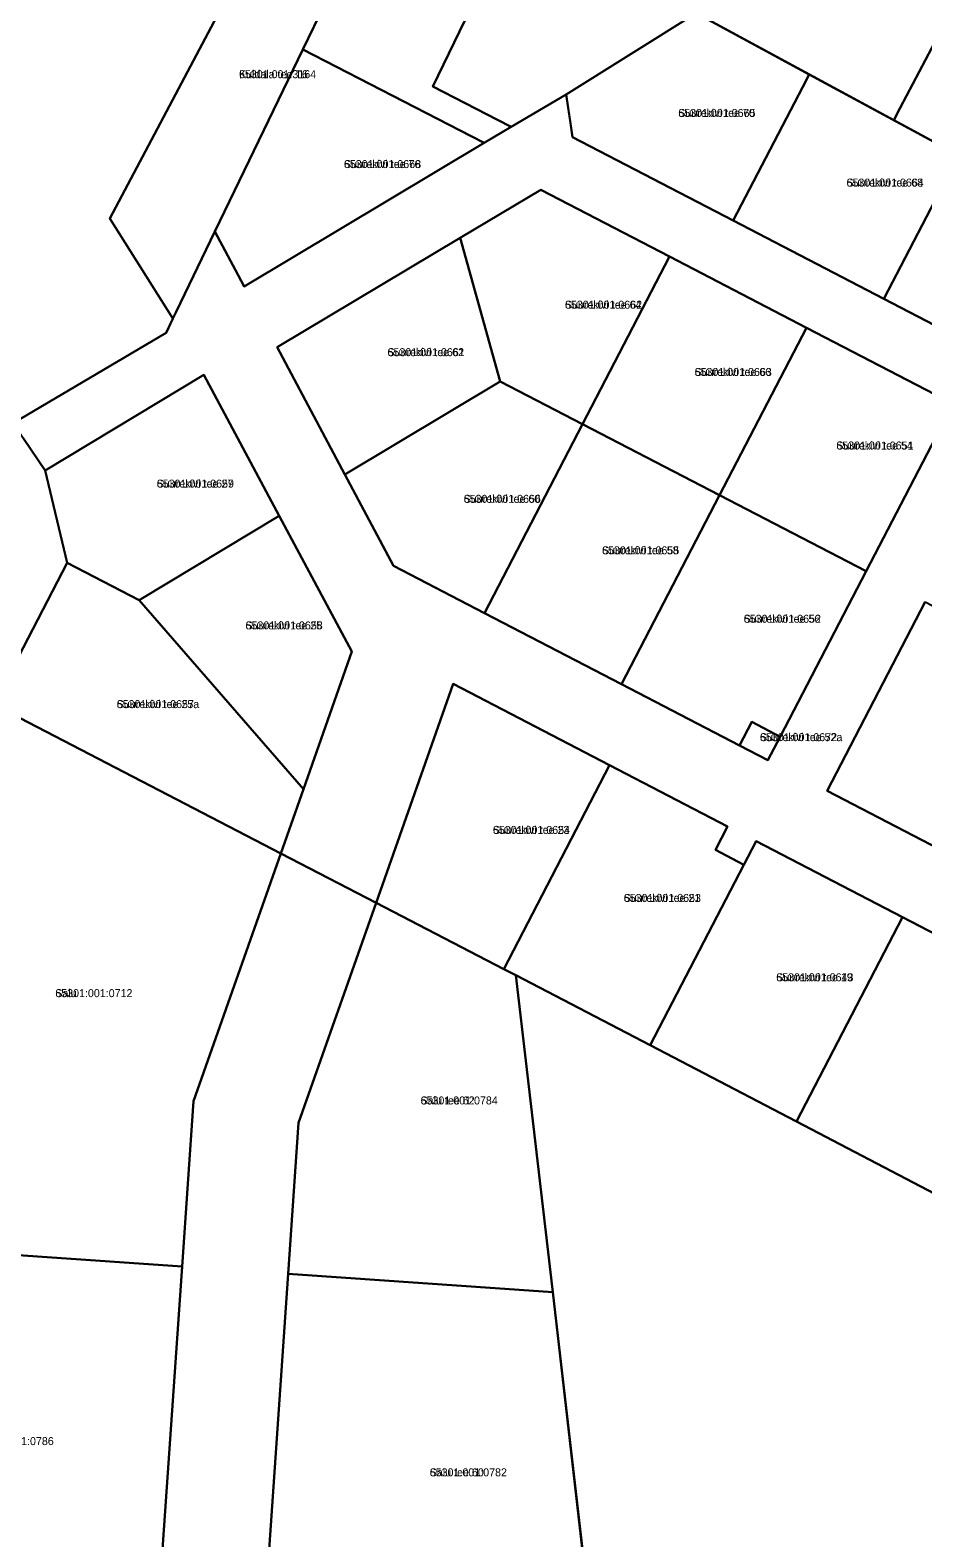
# Model space of a CAD drawing. Extents: x 543236 to 563717, y 6566033 to 6588992.
# Drawn here: x 545424.5 to 545592.2, y 6584755.7 to 6585039 of the extents above; entities that cross this region are included whole.
import ezdxf

# ---------------------------------------------------------------- set-up
doc = ezdxf.new("R2010")
doc.units = 0
for name, color, linetype in [('L_AADRESS', 7, 'Continuous'), ('PIIR', 7, 'Continuous'), ('TUNNUS', 7, 'Continuous')]:
    doc.layers.add(name, color=color, linetype=linetype)

msp = doc.modelspace()

# ---------------------------------------------------------------- linework, layer by layer
at = {"layer": 'PIIR'}
for points in [[(545473.62, 6585068.23), (545439.46, 6585003.59), (545451.28, 6584984.82), (545449.99, 6584982.15), (545421.27, 6584965.16), (545372.09, 6584935.15), (545368.98, 6584936.89), (545361.63, 6584940.84), (545358.12, 6584942.6), (545293.55, 6584977.38), (545384.58, 6585115.49)], [(545493.54, 6585072.24), (545515.81, 6585060.87), (545515.15, 6585059.5), (545500.12, 6585028.41), (545512.27, 6585022.16), (545514.85, 6585020.84), (545509.79, 6585017.81), (545507.34, 6585019.08), (545475.7, 6585035.34), (545492.9, 6585070.91)], [(545473.62, 6585068.23), (545487.93, 6585060.63), (545475.7, 6585035.34), (545459.19, 6585001.19), (545451.9, 6584986.11), (545451.28, 6584984.82), (545439.46, 6585003.59)], [(545515.81, 6585060.87), (545550.91, 6585042.94), (545549.62, 6585042.17), (545525.19, 6585026.92), (545514.85, 6585020.84), (545512.27, 6585022.16), (545500.12, 6585028.41), (545515.15, 6585059.5)], [(545549.62, 6585042.17), (545570.85, 6585030.7), (545569.63, 6585028.37), (545556.58, 6585003.22), (545526.38, 6585018.89), (545525.92, 6585022.04), (545525.19, 6585026.92)], [(545598.65, 6585044.77), (545610.33, 6585038.63), (545599.54, 6585018.11), (545598.92, 6585015.53), (545586.73, 6585022.12), (545587.93, 6585024.39)], [(545475.7, 6585035.34), (545507.34, 6585019.08), (545509.79, 6585017.81), (545464.67, 6584990.84), (545463.54, 6584992.98), (545459.19, 6585001.19)], [(545570.85, 6585030.7), (545598.92, 6585015.53), (545597.72, 6585013.22), (545584.89, 6584988.52), (545556.58, 6585003.22), (545569.63, 6585028.37)], [(545598.92, 6585015.53), (545625.66, 6585001.08), (545624.52, 6584998.89), (545611.88, 6584974.52), (545584.89, 6584988.52), (545597.72, 6585013.22)], [(545470.88, 6584979.41), (545483.58, 6584955.54), (545492.74, 6584938.33), (545509.85, 6584929.45), (545535.59, 6584916.09), (545557.78, 6584904.58), (545563.1, 6584901.81), (545565.4, 6584906.25), (545581.53, 6584937.32), (545597.88, 6584968.82), (545570.36, 6584983.1), (545544.63, 6584996.46), (545520.42, 6585009.02), (545505.27, 6584999.96)], [(545520.42, 6585009.02), (545544.63, 6584996.46), (545528.27, 6584964.95), (545512.78, 6584973), (545505.27, 6584999.96)], [(545470.88, 6584979.41), (545505.27, 6584999.96), (545512.78, 6584973), (545483.58, 6584955.54)], [(545544.63, 6584996.46), (545570.36, 6584983.1), (545554.01, 6584951.6), (545528.27, 6584964.95)], [(545570.36, 6584983.1), (545597.88, 6584968.82), (545581.53, 6584937.32), (545554.01, 6584951.6)], [(545427.3, 6584956.26), (545457.12, 6584974.22), (545471.28, 6584947.73), (545444.97, 6584931.88), (545431.4, 6584938.91)], [(545512.78, 6584973), (545528.27, 6584964.95), (545509.85, 6584929.45), (545492.74, 6584938.33), (545483.58, 6584955.54)], [(545372.09, 6584935.15), (545421.27, 6584965.16), (545423.21, 6584962.28), (545427.3, 6584956.26), (545431.4, 6584938.91), (545417.57, 6584912.29), (545403.48, 6584919.59), (545374.31, 6584934.05)], [(545528.27, 6584964.95), (545554.01, 6584951.6), (545535.59, 6584916.09), (545509.85, 6584929.45)], [(545554.01, 6584951.6), (545581.53, 6584937.32), (545565.4, 6584906.25), (545560.08, 6584909.01), (545557.78, 6584904.58), (545535.59, 6584916.09)], [(545444.97, 6584931.88), (545471.28, 6584947.73), (545484.9, 6584922.24), (545475.8, 6584896.41)], [(545431.4, 6584938.91), (545444.97, 6584931.88), (545475.8, 6584896.41), (545471.54, 6584884.32), (545417.57, 6584912.29)], [(545592.62, 6584931.56), (545617.6, 6584918.59), (545620.14, 6584917.28), (545601.71, 6584881.77), (545574.2, 6584896.05)], [(545403.48, 6584919.59), (545417.57, 6584912.29), (545471.54, 6584884.32), (545455.14, 6584837.79), (545453, 6584806.71), (545386.81, 6584811.27), (545395.81, 6584869.64)], [(545503.96, 6584916.17), (545533.34, 6584900.92), (545513.45, 6584862.59), (545489.47, 6584875.03)], [(545560.08, 6584909.01), (545565.4, 6584906.25), (545563.1, 6584901.81), (545557.78, 6584904.58)], [(545533.34, 6584900.92), (545555.53, 6584889.4), (545553.23, 6584884.96), (545558.56, 6584882.2), (545540.95, 6584848.28), (545515.72, 6584861.42), (545513.45, 6584862.59)], [(545560.86, 6584886.64), (545588.37, 6584872.36), (545568.44, 6584833.94), (545540.95, 6584848.28), (545558.56, 6584882.2)], [(545489.47, 6584875.03), (545513.45, 6584862.59), (545515.72, 6584861.42), (545522.71, 6584801.88), (545472.95, 6584805.34), (545474.91, 6584833.7)], [(545588.37, 6584872.36), (545615.89, 6584858.08), (545595.9, 6584819.6), (545568.44, 6584833.94)], [(545522.71, 6584801.88), (545515.72, 6584861.42), (545540.95, 6584848.28), (545568.44, 6584833.94), (545595.9, 6584819.6), (545623.37, 6584805.21), (545650.89, 6584790.87), (545654.59, 6584788.95), (545726.79, 6584620.99), (545552.43, 6584545.79), (545548.01, 6584583.61), (545542.31, 6584632.89), (545539.87, 6584653.16), (545534.53, 6584699.52), (545531.48, 6584725.86), (545531.11, 6584728.87), (545530.7, 6584731.91)], [(545386.81, 6584811.27), (545453, 6584806.71), (545448.22, 6584737.35), (545448.03, 6584734.59), (545411.55, 6584737.1), (545375.78, 6584739.56), (545386, 6584805.97)], [(545472.95, 6584805.34), (545522.71, 6584801.88), (545530.76, 6584731.87), (545531.11, 6584728.87), (545500.59, 6584730.97), (545467.99, 6584733.21), (545468.2, 6584736.24)]]:
    msp.add_lwpolyline(points, close=True, dxfattribs=at)
for points in [[(545598.65, 6585044.77), (545587.93, 6585024.39), (545586.73, 6585022.12), (545549.62, 6585042.17)], [(545421.27, 6584965.16), (545449.99, 6584982.15), (545451.9, 6584986.11), (545459.19, 6585001.19), (545463.54, 6584992.98), (545464.67, 6584990.84), (545509.79, 6585017.81), (545514.85, 6585020.84), (545525.19, 6585026.92), (545525.57, 6585024.34), (545526.38, 6585018.89), (545556.58, 6585003.22), (545584.89, 6584988.52), (545611.88, 6584974.52)], [(545810.27, 6584757.2), (545772.99, 6584776.54), (545735.71, 6584795.89), (545698.44, 6584815.24), (545670.92, 6584829.52), (545643.41, 6584843.8), (545615.89, 6584858.08), (545588.37, 6584872.36), (545560.86, 6584886.64), (545558.56, 6584882.2), (545553.23, 6584884.96), (545555.53, 6584889.4), (545533.34, 6584900.92), (545503.96, 6584916.17), (545489.47, 6584875.03), (545471.54, 6584884.32), (545475.8, 6584896.41), (545484.9, 6584922.24), (545471.28, 6584947.73), (545457.12, 6584974.22), (545427.3, 6584956.26), (545423.21, 6584962.28)], [(545592.62, 6584931.56), (545574.2, 6584896.05), (545601.71, 6584881.77)], [(545448.22, 6584737.35), (545453, 6584806.71), (545455.14, 6584837.79), (545471.54, 6584884.32), (545489.47, 6584875.03), (545474.91, 6584833.7), (545472.95, 6584805.34), (545468.2, 6584736.24)]]:
    msp.add_lwpolyline(points, dxfattribs=at)

# ---------------------------------------------------------------- texts
at = {"layer": 'L_AADRESS'}
for s, p in [('Kuldala tee T6', (545463.7, 6585029.98)), ('Suurekivi tee 70', (545546.25, 6585022.7)), ('Suurekivi tee 76', (545483.42, 6585013.09)), ('Suurekivi tee 68', (545577.87, 6585009.61)), ('Suurekivi tee 64', (545524.95, 6584986.67)), ('Suurekivi tee 62', (545491.61, 6584977.75)), ('Suurekivi tee 66', (545549.32, 6584974.03)), ('Suurekivi tee 54', (545575.95, 6584960.21)), ('Suurekivi tee 27', (545448.25, 6584953.05)), ('Suurekivi tee 60', (545505.93, 6584950.19)), ('Suurekivi tee 58', (545531.93, 6584940.52)), ('Suurekivi tee 56', (545558.56, 6584927.66)), ('Suurekivi tee 25', (545464.93, 6584926.41)), ('Suurekivi tee 25a', (545440.73, 6584911.62)), ('Suurekivi tee 52a', (545561.59, 6584905.41)), ('Suurekivi tee 23', (545511.41, 6584887.98)), ('Suurekivi tee 21', (545536.01, 6584875.2)), ('Suurekivi tee 19', (545564.66, 6584860.29)), ('Salu', (545429.18, 6584857.31)), ('Salu tee 62', (545497.83, 6584837.15)), ('Salu tee 60', (545499.55, 6584767.27))]:
    msp.add_text(s, height=1.5, dxfattribs=at).set_placement(p)
at = {"layer": 'TUNNUS'}
for s, p in [('65301:001:3164', (545463.7, 6585029.98)), ('65301:001:0665', (545546.25, 6585022.7)), ('65301:001:0668', (545483.42, 6585013.09)), ('65301:001:0664', (545577.87, 6585009.61)), ('65301:001:0662', (545524.95, 6584986.67)), ('65301:001:0661', (545491.61, 6584977.75)), ('65301:001:0663', (545549.32, 6584974.03)), ('65301:001:0651', (545575.95, 6584960.21)), ('65301:001:0659', (545448.25, 6584953.05)), ('65301:001:0656', (545505.93, 6584950.19)), ('65301:001:0655', (545531.93, 6584940.52)), ('65301:001:0652', (545558.56, 6584927.66)), ('65301:001:0658', (545464.93, 6584926.41)), ('65301:001:0657', (545440.73, 6584911.62)), ('65301:001:0672', (545561.59, 6584905.41)), ('65301:001:0654', (545511.41, 6584887.98)), ('65301:001:0653', (545536.01, 6584875.2)), ('65301:001:0643', (545564.66, 6584860.29)), ('65301:001:0712', (545429.18, 6584857.31)), ('65301:001:0784', (545497.83, 6584837.15)), ('65301:001:0786', (545414.39, 6584773.14)), ('65301:001:0782', (545499.55, 6584767.27))]:
    msp.add_text(s, height=1.5, dxfattribs=at).set_placement(p)

doc.saveas('drawing.dxf')
